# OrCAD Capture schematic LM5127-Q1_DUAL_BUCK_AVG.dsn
size Custom; title: LM5127-Q1 2.2MHz Wide VIN Automotive Front-stage; rev: 1.0; note: Datasheet: NA     EVM: NA; note: Synchronous Step Down Converter
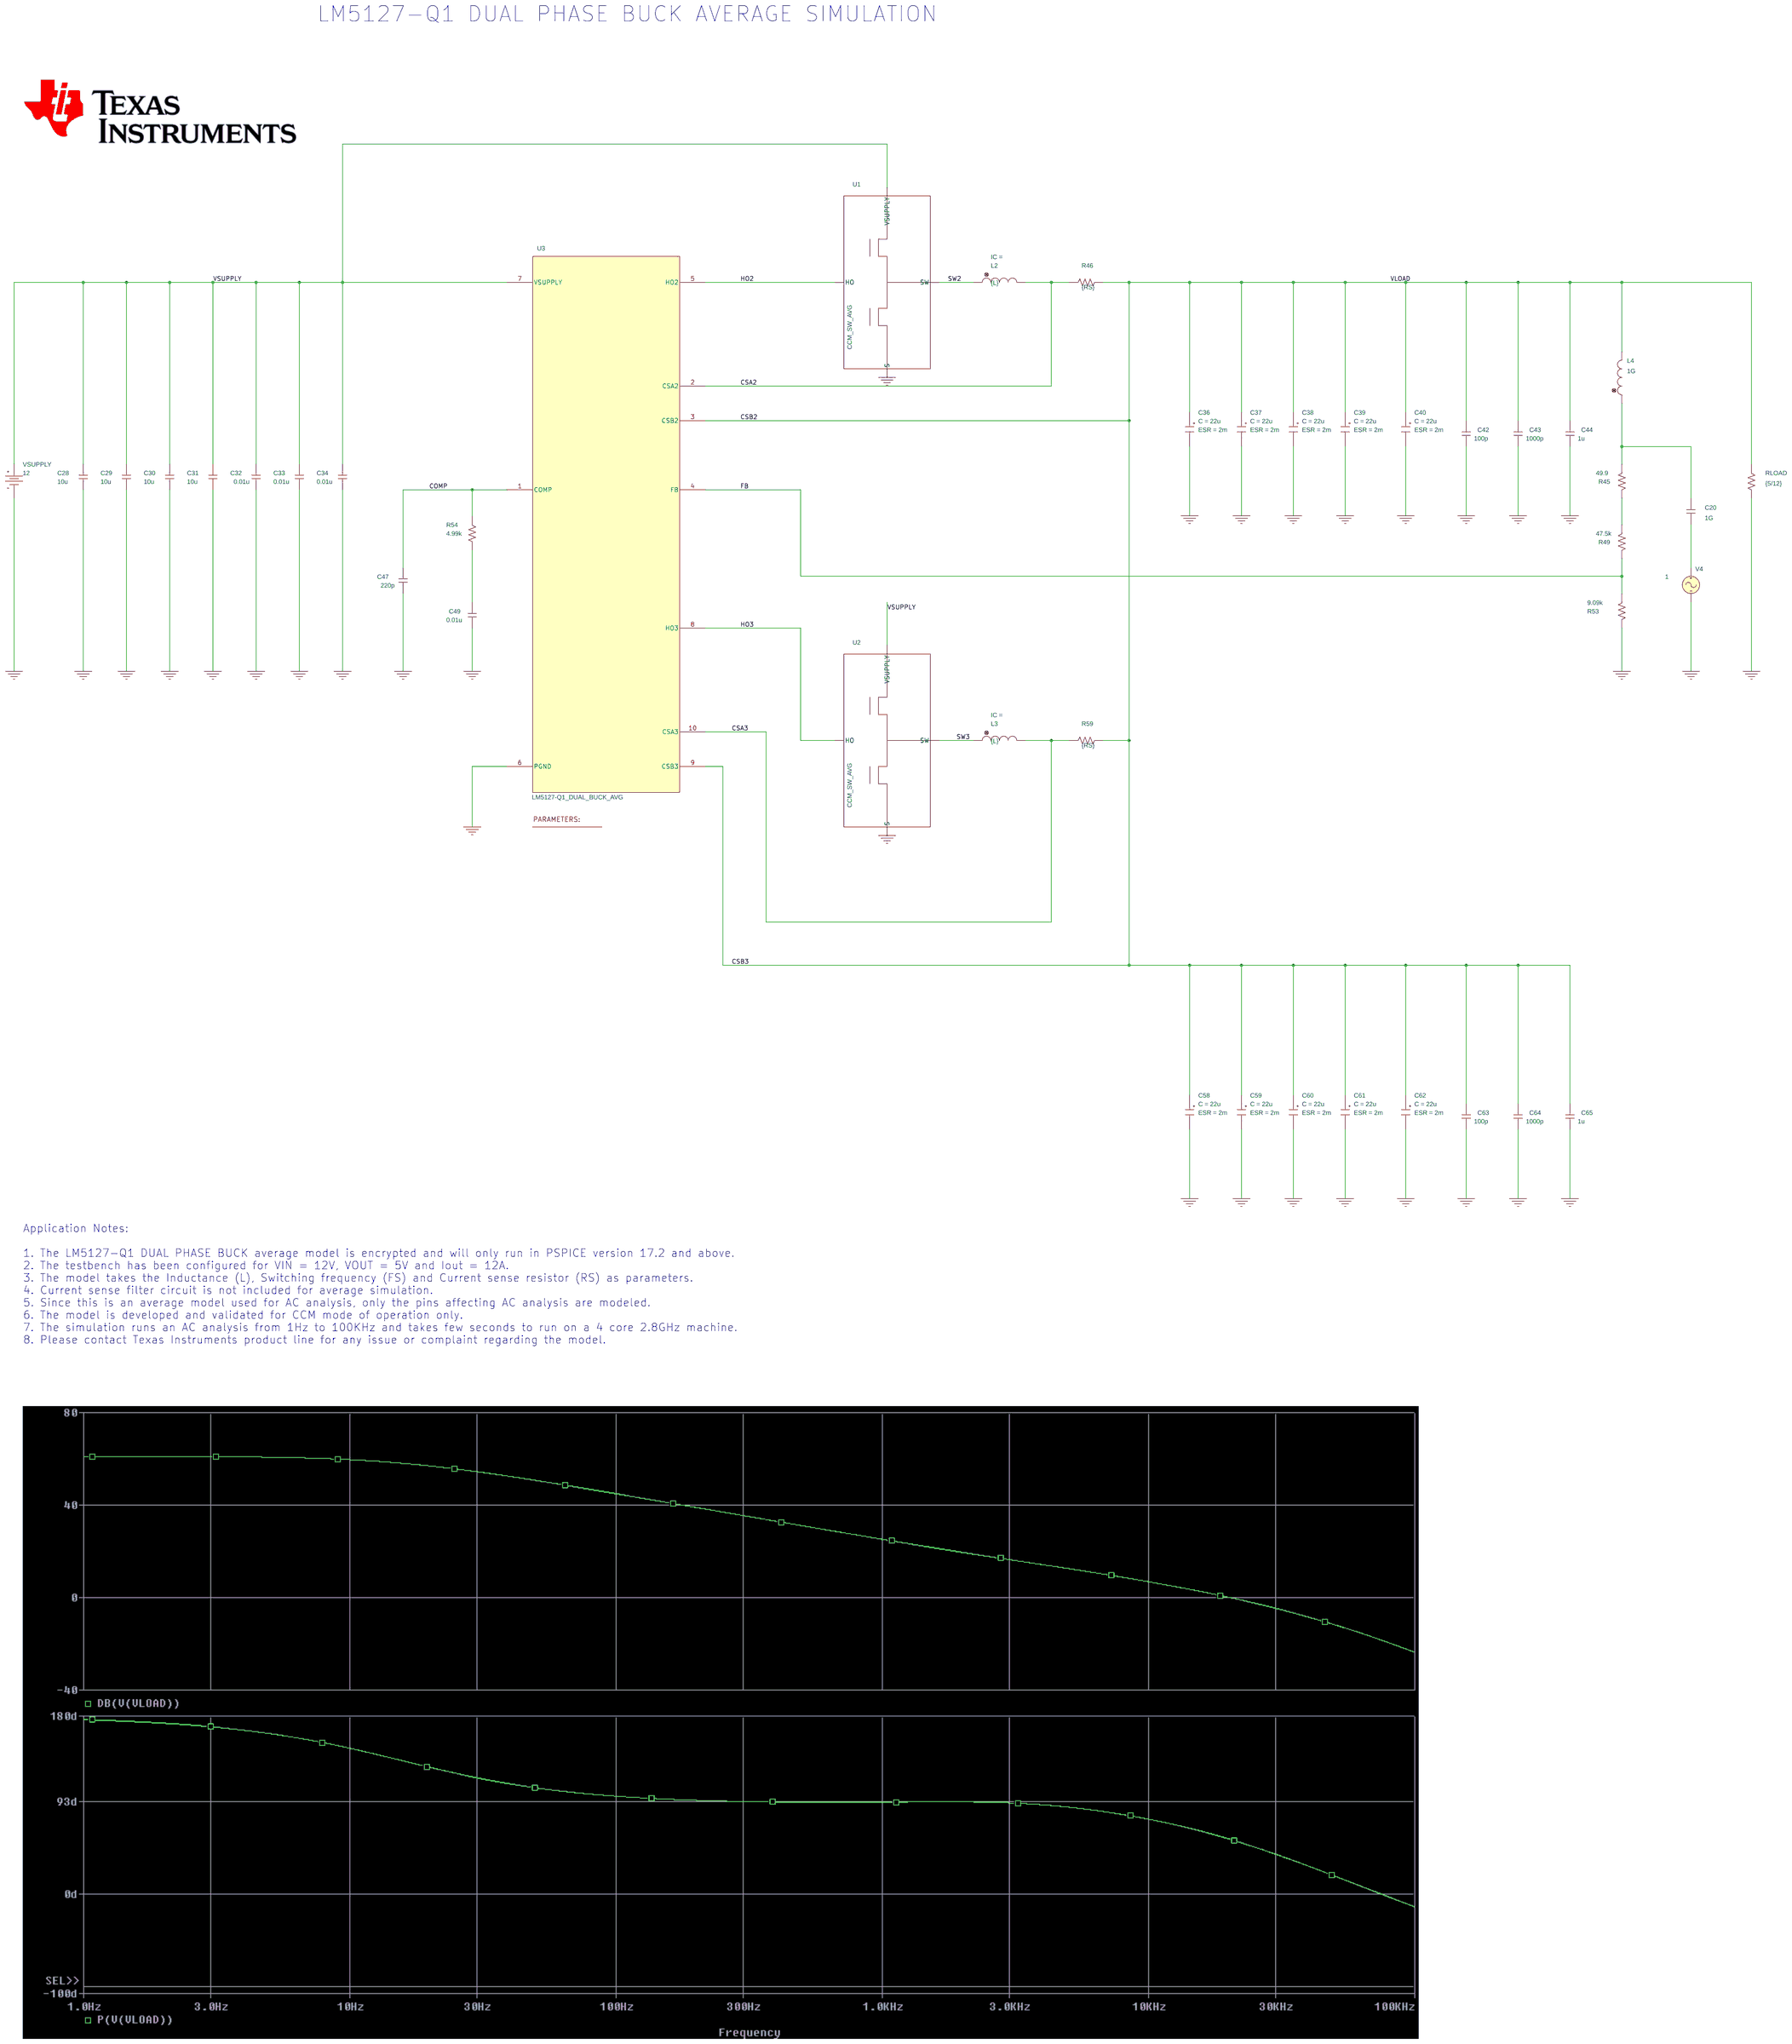
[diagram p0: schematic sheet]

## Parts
1  PARAM
C20  1G  [RAD/CK05]
C28  10u  [RAD/CK05]
C29  10u  [RAD/CK05]
C30  10u  [RAD/CK05]
C31  10u  [RAD/CK05]
C32  0.01u  [RAD/CK05]
C33  0.01u  [RAD/CK05]
C34  0.01u  [RAD/CK05]
C36  CESR
C37  CESR
C38  CESR
C39  CESR
C40  CESR
C42  100p  [RAD/CK05]
C43  1000p  [RAD/CK05]
C44  1u  [RAD/CK05]
C47  220p  [RAD/CK05]
C49  0.01u  [RAD/CK05]
C58  CESR
C59  CESR
C60  CESR
C61  CESR
C62  CESR
C63  100p  [RAD/CK05]
C64  1000p  [RAD/CK05]
C65  1u  [RAD/CK05]
L2  {L}  [DISC/.350x.175/LS.200x.100/.034]
L3  {L}  [DISC/.350x.175/LS.200x.100/.034]
L4  1G  [DISC/.350x.175/LS.200x.100/.034]
R45  49.9  [AX/RC05]
R46  {RS}  [AX/RC05]
R49  47.5k  [AX/RC05]
R53  9.09k  [AX/RC05]
R54  4.99k  [AX/RC05]
R59  {RS}  [AX/RC05]
RLOAD  {5/12}  [AX/RC05]
U1  CCM_SW_AVG  [DRB0008A]
U2  CCM_SW_AVG  [DRB0008A]
U3  LM5127-Q1_DUAL_BUCK_AVG
V4  VAC
VSUPPLY  VDC

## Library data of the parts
1 = PARAM: FS: 440k; L: 2.4u; RS: 5m
C20 C28-C34 C42-C44 C47 C49 C63-C65 = C
C36-C40 C58-C62 = CESR_0: C: 22u; ESR: 2m; PSpiceTemplate: X^@REFDES %IN %OUT @MODEL PARAMS:  ?C|C=@C||C=100u|  ?ESR|ESR=@ESR||ESR=0.01|; X: 1
L2-L4 = L
R45 R46 R49 R53 R54 R59 RLOAD = R
U1 = CCM_SW_AVG
U2 = CCM_SW_AVG_1
U3 = LM5127-Q1_DUAL_BUCK_AVG
V4 = VAC: ACMAG: 1; ACPHASE: 0
VSUPPLY = VDC: DC: 12

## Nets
0: C28.2 C29.2 C30.2 C31.2 C32.2 C33.2 C34.2 C36.2(OUT) C37.2(OUT) C38.2(OUT) C39.2(OUT) C40.2(OUT) C42.2 C43.2 C44.2 C47.2 C49.2 C58.2(OUT) C59.2(OUT) C60.2(OUT) C61.2(OUT) C62.2(OUT) C63.2 C64.2 C65.2 R53.2 RLOAD.2 U1.S U2.S U3.6(PGND) V4.2(-) VSUPPLY.1(-)
COMP: C47.1 R54.1 U3.1(COMP)
CSA2: L2.2 R46.1 U3.2(CSA2)
CSA3: L3.2 R59.1 U3.10(CSA3)
CSB2: C36.1(IN) C37.1(IN) C38.1(IN) C39.1(IN) C40.1(IN) C42.1 C43.1 C44.1 C58.1(IN) C59.1(IN) C60.1(IN) C61.1(IN) C62.1(IN) C63.1 C64.1 C65.1 L4.2 R46.2 R59.2 RLOAD.1 U3.3(CSB2) U3.9(CSB3)
FB: R49.2 R53.1 U3.4(FB)
HO2: U1.HO U3.5(HO2)
HO3: U2.HO U3.8(HO3)
SW2: L2.1 U1.SW
SW3: L3.1 U2.SW
VSUPPLY: C28.1 C29.1 C30.1 C31.1 C32.1 C33.1 C34.1 U1.VSUPPLY U2.VSUPPLY U3.7(VSUPPLY) VSUPPLY.0(+)
N307172: C49.1 R54.2
N311691: R45.2 R49.1
N16772710: C20.1 L4.1 R45.1
N16772752: C20.2 V4.1(+)

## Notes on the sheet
- LM5127-Q1 DUAL PHASE BUCK AVERAGE SIMULATION
- Application Notes:
  1. The LM5127-Q1 DUAL PHASE BUCK average model is encrypted and will only run in PSPICE version 17.2 and above.
  2. The testbench has been configured for VIN = 12V, VOUT = 5V and Iout = 12A.
  3. The model takes the Inductance (L), Switching frequency (FS) and Current sense resistor (RS) as parameters.
  4. Current sense filter circuit is not included for average simulation.
  5. Since this is an average model used for AC analysis, only the pins affecting AC analysis are modeled.
  6. The model is developed and validated for CCM mode of operation only.
  7. The simulation runs an AC analysis from 1Hz to 100KHz and takes few seconds to run on a 4 core 2.8GHz machine.
  8. Please contact Texas Instruments product line for any issue or complaint regarding the model.
